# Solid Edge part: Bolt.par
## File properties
Author: Vicky Raina
Template: Normal.par
Last saved by: Administrator
Revision: 2
Application: Solid Edge
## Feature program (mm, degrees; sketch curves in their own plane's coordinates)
sketch for "unnamed Protrusion 1" plane through (0, 0, 0) normal (0, 0, 1) x-axis (1, 0, 0)
  line (-12, 12) -> (-12, -12)
  line (-12, -12) -> (12, -12)
  line (12, -12) -> (12, 12)
  line (12, 12) -> (-12, 12)
extrude "unnamed Protrusion 1" add finite 8 along +normal
sketch for "unnamed Protrusion 2" plane through (0, 0, 0) normal (0, 0, 1) x-axis (1, 0, 0)
  circle centre (0, 0) radius 6
extrude "unnamed Protrusion 2" add finite 104 along +normal
sketch for "unnamed RevolvedCutout 1" plane through (-12, 12, 4) normal (-0.707107, -0.707107, 0) x-axis (0, 0, -1)
  arc centre (-3, 7) radius 7 from (-3, 0) to (4, 7) ccw
  line (4, 7) -> (4, 0)
  line (-3, 0) -> (4, 0)
revolve "unnamed RevolvedCutout 1" cut full turn 360 deg about sketch line (9.5376, 16.9706) -> (-8.8435, 16.9706)
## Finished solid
Body 1: solid body, 9 faces, 15 edges, 8 vertices.
  Faces by surface: plane 7, cylinder 1, torus 1
  Edges by curve: line 8, intersection 4, circle 3
Bounding box of the edges (mm; curved faces can reach further): 24.000 x 24.000 x 104.000, from (-12, -12, 0) to (12, 12, 104).
Cylindrical faces by radius (mm): R6 x1
Toroidal faces (ring radius, tube radius in mm): R9.9706 r7 x1
Planar faces by outward normal: +x 1, +y 1, +z 2, -x 1, -y 1, -z 1
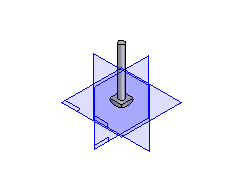
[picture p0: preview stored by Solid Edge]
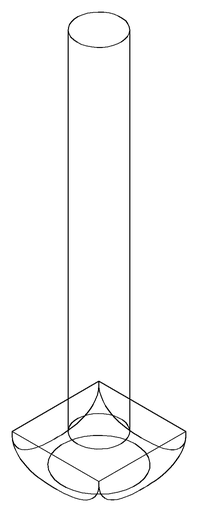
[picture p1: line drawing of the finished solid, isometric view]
